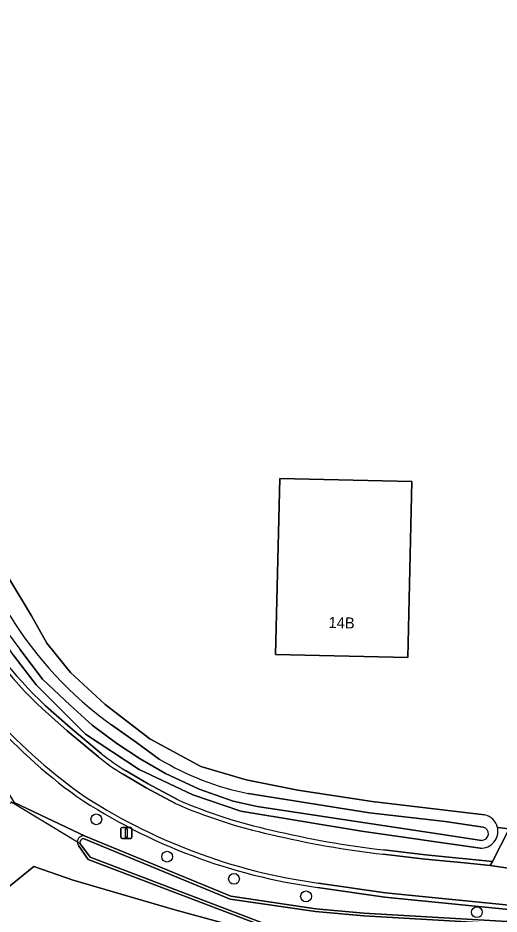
# Model space of a CAD drawing. Extents: x 162510 to 163918, y 388494 to 389774.
# Drawn here: x 162919.9 to 162963.6, y 388968.2 to 389049.6 of the extents above; entities that cross this region are included whole.
import ezdxf

# ---------------------------------------------------------------- set-up
doc = ezdxf.new("R2010")
doc.units = 0
for name, color, linetype in [('IMGEO_Boom', 7, 'Continuous'), ('IMGEO_Duiker', 7, 'Continuous'), ('IMGEO_Erf', 7, 'Continuous'), ('IMGEO_Grasland_agrarisch', 7, 'Continuous'), ('IMGEO_Grasland_overig', 7, 'Continuous'), ('IMGEO_Lichtmast', 7, 'Continuous'), ('IMGEO_Oever', 7, 'Continuous'), ('IMGEO_Pand', 7, 'Continuous'), ('IMGEO_Pand_nummerreeks', 7, 'Continuous'), ('IMGEO_Rijbaan_lokaal_gesloten', 7, 'Continuous'), ('IMGEO_Rijbaan_lokaal_halfverhard', 7, 'Continuous'), ('IMGEO_Rijbaan_lokaal_open', 7, 'Continuous'), ('IMGEO_Waterloop', 7, 'Continuous')]:
    doc.layers.add(name, color=color, linetype=linetype)

msp = doc.modelspace()

# ---------------------------------------------------------------- linework, layer by layer
at = {"layer": 'IMGEO_Boom'}
for centre in [(162927.001, 388976.769), (162933.436, 388973.374), (162939.51, 388971.359), (162946.06, 388969.768), (162961.588, 388968.328)]:
    msp.add_circle(centre, 0.489, dxfattribs=at)
at = {"layer": 'IMGEO_Duiker'}
msp.add_lwpolyline([(162925.55, 388974.52), (162925.278, 388974.684), (162919.381, 388978.255), (162919.231, 388978.346)], dxfattribs=at)
at = {"layer": 'IMGEO_Erf'}
for points in [[(162963.458, 388976.024), (162964.53, 388975.919), (162971.105, 388975.277), (162985.529, 388974.355), (162985.891, 388974.332), (163003.132, 388973.537), (163003.268, 388973.532), (163003.178, 388973.126), (163010.129, 388973.107), (163010.129, 388973.525), (163011.598, 388973.525), (163015.346, 388973.525), (163010.383, 389006.948), (163001.868, 389067.016)], [(162917.331, 389001.487), (162921.109, 388995.245), (162922.506, 388992.781), (162924.641, 388990.111), (162927.804, 388987.195), (162931.869, 388984.074), (162936.51, 388981.566), (162940.613, 388980.351), (162945.319, 388979.431), (162952.054, 388978.404), (162962.289, 388977.181)]]:
    msp.add_lwpolyline(points, dxfattribs=at)
msp.add_lwpolyline([(162955.677, 389007.464), (162955.304, 388991.467), (162943.286, 388991.753), (162943.667, 389007.749)], close=True, dxfattribs=at)
msp.add_arc((162961.959, 388975.679), 1.538, 12.97569, 77.61549, dxfattribs=at)
at = {"layer": 'IMGEO_Grasland_agrarisch'}
msp.add_lwpolyline([(162965.269, 388906.51), (162965.295, 388907.571), (162970.507, 388960.823), (162969.722, 388963.115), (162943.576, 388965.984), (162934.148, 388968.56), (162924.889, 388971.244), (162921.313, 388972.477), (162913.718, 388966.327), (162905.083, 388967.364), (162899.047, 388963.626), (162890.416, 388958.224), (162881.009, 388955.532), (162875.047, 388956.022), (162874.432, 388960.337)], dxfattribs=at)
at = {"layer": 'IMGEO_Grasland_overig'}
for points in [[(162961.88, 388974.143), (162951.099, 388975.683), (162940.134, 388977.514), (162935.781, 388978.992), (162930.904, 388981.309), (162926.018, 388984.505), (162921.542, 388989.001), (162919.446, 388991.713), (162916.571, 388996.046), (162914.292, 388999.844), (162909.816, 389007.729), (162906.182, 389015.741), (162904.051, 389020.029), (162902.408, 389023.626), (162901.284, 389026.429), (162899.191, 389030.377)], [(162890.275, 389028.321), (162906.761, 389000), (162914.021, 388987.018), (162919.521, 388978.287), (162925.982, 388975.254), (162939.232, 388969.776), (162946.964, 388968.638), (162951.321, 388968.254), (162966.391, 388967.363), (162970.783, 388966.255), (162971.31, 388964.515), (162972.188, 388961.62), (162974.481, 388958.888)], [(162922.374, 388987.09), (162924.622, 388985.127), (162927.452, 388982.75)], [(162929.651, 388981.209), (162931.71, 388979.994), (162934.378, 388978.562)], [(162925.982, 388975.254), (162919.521, 388978.287), (162919.381, 388978.255), (162916.496, 388977.585), (162877.491, 388960.617), (162874.432, 388960.337)], [(162953.123, 388973.988), (162956.928, 388973.533), (162962.999, 388972.942), (162964.53, 388975.919), (162963.458, 388976.024)], [(162874.432, 388960.337), (162875.047, 388956.022), (162881.009, 388955.532), (162890.416, 388958.224), (162899.047, 388963.626), (162905.083, 388967.364), (162913.718, 388966.327), (162921.313, 388972.477), (162924.889, 388971.244), (162934.148, 388968.56), (162943.576, 388965.984), (162969.722, 388963.115), (162969.194, 388964.658), (162943.616, 388966.516), (162926.272, 388973.119), (162925.379, 388974.383)], [(162970.158, 388968.16), (162965.692, 388968.446), (162953.235, 388969.706), (162947.107, 388970.584)]]:
    msp.add_lwpolyline(points, dxfattribs=at)
for centre, radius, start, end in [((162953.538, 389019.707), 45.112, 210.91686, 226.30497), ((162955.293, 389020.184), 51.114, 209.11016, 233.98533), ((162938.618, 388996.345), 17.593, 230.60151, 239.35502), ((162954.136, 389022.301), 52.193, 236.37965, 262.25982), ((162952.816, 389020.914), 46.191, 246.47421, 257.64713), ((162962.813, 389058.391), 84.957, 256.46826, 263.45098), ((162961.958, 388975.68), 1.539, 267.0987, 12.91369), ((162925.842, 388974.707), 0.565, 75.64478, 182.34657), ((162925.842, 388974.706), 0.565, 182.22454, 214.87363)]:
    msp.add_arc(centre, radius, start, end, dxfattribs=at)
at = {"layer": 'IMGEO_Lichtmast'}
for p, q in [((162929.236, 388975.135), (162929.236, 388975.935)), ((162929.236, 388975.935), (162929.236, 388975.135)), ((162929.336, 388976.035), (162930.126, 388976.035)), ((162930.126, 388976.035), (162929.336, 388976.035)), ((162930.226, 388975.935), (162930.226, 388975.135)), ((162930.226, 388975.135), (162930.226, 388975.935)), ((162930.126, 388975.035), (162929.336, 388975.035)), ((162929.336, 388975.035), (162930.126, 388975.035))]:
    msp.add_line(p, q, dxfattribs=at)
msp.add_lwpolyline([(162929.656, 388975.91), (162929.806, 388975.91), (162929.806, 388975.16), (162929.656, 388975.16), (162929.656, 388975.91)], dxfattribs=at)
for centre, start, end in [((162929.336, 388975.935), 90, 180), ((162929.336, 388975.935), 90, 180), ((162930.126, 388975.935), 0, 90), ((162930.126, 388975.935), 360, 90), ((162929.336, 388975.135), 180, 270), ((162929.336, 388975.135), 180, 270), ((162930.126, 388975.135), 270, 0), ((162930.126, 388975.135), 270, 0)]:
    msp.add_arc(centre, 0.1, start, end, dxfattribs=at)
at = {"layer": 'IMGEO_Oever'}
for points in [[(162962.289, 388977.181), (162952.054, 388978.404), (162945.319, 388979.431), (162940.613, 388980.351), (162936.51, 388981.566), (162931.869, 388984.074), (162927.804, 388987.195), (162924.641, 388990.111), (162922.506, 388992.781), (162921.109, 388995.245), (162917.331, 389001.487)], [(162962.001, 388974.859), (162959.25, 388975.27), (162941.605, 388977.932), (162939.439, 388978.425), (162936.358, 388979.523), (162933.289, 388980.94), (162930.973, 388982.26), (162928.874, 388983.661), (162926.625, 388985.324), (162924.634, 388987.131), (162922.108, 388989.507), (162920.041, 388992.229)], [(162919.446, 388991.713), (162921.542, 388989.001), (162926.018, 388984.505), (162930.904, 388981.309), (162935.781, 388978.992), (162940.134, 388977.514), (162951.099, 388975.683), (162961.88, 388974.143)], [(162928.367, 388985.352), (162930.666, 388983.75), (162932.72, 388982.251)], [(162940.81, 388979.11), (162951.837, 388977.364)], [(162951.837, 388977.364), (162958.695, 388976.563), (162962.153, 388976.067)], [(162925.911, 388975.006), (162939.163, 388969.527), (162946.934, 388968.383), (162951.302, 388967.998), (162966.352, 388967.108), (162970.579, 388966.042), (162971.064, 388964.44), (162971.927, 388961.595), (162966.53, 388908.206)], [(162966.787, 388908.195), (162972.188, 388961.62), (162971.31, 388964.515), (162970.783, 388966.255), (162966.391, 388967.363), (162951.321, 388968.254), (162946.964, 388968.638), (162939.232, 388969.776), (162925.982, 388975.254)], [(162925.379, 388974.383), (162926.272, 388973.119), (162943.616, 388966.516), (162969.194, 388964.658), (162969.722, 388963.115), (162970.507, 388960.823), (162965.295, 388907.571), (162965.269, 388906.51)], [(162965.551, 388907.555), (162970.768, 388960.853), (162969.965, 388963.198), (162969.382, 388964.902), (162943.672, 388966.769), (162926.437, 388973.331), (162925.55, 388974.52)]]:
    msp.add_lwpolyline(points, dxfattribs=at)
for centre, radius, start, end in [((162985.083, 389040.407), 80.942, 209.85069, 216.52824), ((162948.731, 389013.515), 34.754, 211.65165, 234.13095), ((162945.921, 389004.264), 25.668, 239.04829, 258.5136), ((162961.959, 388975.679), 1.538, 12.97569, 77.61549), ((162961.958, 388975.68), 1.539, 267.0987, 12.91369), ((162962.026, 388975.469), 0.611, 267.61328, 78.0433), ((162925.842, 388974.707), 0.565, 75.64478, 182.34657), ((162925.856, 388974.67), 0.341, 80.66528, 206.12491), ((162925.842, 388974.706), 0.565, 182.22454, 214.87363)]:
    msp.add_arc(centre, radius, start, end, dxfattribs=at)
at = {"layer": 'IMGEO_Pand'}
msp.add_lwpolyline([(162955.304, 388991.467), (162955.677, 389007.464), (162943.667, 389007.749), (162943.286, 388991.753)], close=True, dxfattribs=at)
at = {"layer": 'IMGEO_Rijbaan_lokaal_gesloten'}
for points in [[(162927.195, 388982.444), (162924.365, 388984.821), (162922.098, 388986.801)], [(162934.189, 388978.21), (162931.521, 388979.642), (162929.447, 388980.865)], [(163060.658, 388969.221), (163043.395, 388969.279), (163026.878, 388969.344), (163019.275, 388969.441), (163016.375, 388969.489), (163010.694, 388969.666), (163006.164, 388969.852), (163001.869, 388970.009), (162995.115, 388970.321), (162989.16, 388970.649), (162986.023, 388970.77), (162985.329, 388970.797), (162980.065, 388971.129), (162974.827, 388971.464), (162970.89, 388971.741), (162967.254, 388971.997), (162965.448, 388972.167), (162962.802, 388972.559), (162960.469, 388972.811), (162956.88, 388973.136), (162953.077, 388973.591)], [(162947.161, 388970.98), (162953.292, 388970.102), (162965.732, 388968.844), (162970.174, 388968.559), (162975.389, 388968.225), (162985.053, 388967.564), (162990.798, 388967.159), (162991.481, 388967.111), (163004.846, 388966.436), (163005.318, 388966.412), (163012.759, 388966.272), (163018.447, 388966.138), (163027.251, 388966.034), (163035.819, 388965.997), (163049.064, 388965.828), (163059.249, 388965.846), (163068.574, 388965.898)]]:
    msp.add_lwpolyline(points, dxfattribs=at)
for centre, radius, start, end in [((162953.569, 389019.735), 45.553, 210.93385, 226.30203), ((162955.268, 389020.162), 50.682, 209.10323, 233.99307), ((162938.634, 388996.363), 18.016, 230.58577, 239.34144), ((162954.145, 389022.323), 51.816, 236.40293, 262.25355), ((162952.767, 389020.73), 46.402, 246.39887, 257.65864), ((162962.764, 389058.132), 85.094, 256.46551, 263.46357)]:
    msp.add_arc(centre, radius, start, end, dxfattribs=at)
at = {"layer": 'IMGEO_Rijbaan_lokaal_halfverhard'}
for points in [[(162922.098, 388986.801), (162924.365, 388984.821), (162927.195, 388982.444)], [(162927.452, 388982.75), (162924.622, 388985.127), (162922.374, 388987.09)], [(162929.447, 388980.865), (162931.521, 388979.642), (162934.189, 388978.21)], [(162934.378, 388978.562), (162931.71, 388979.994), (162929.651, 388981.209)], [(162953.077, 388973.591), (162956.88, 388973.136), (162960.469, 388972.811), (162962.802, 388972.559), (162962.999, 388972.942), (162956.928, 388973.533), (162953.123, 388973.988)], [(162947.107, 388970.584), (162953.235, 388969.706), (162965.692, 388968.446), (162970.158, 388968.16), (162970.174, 388968.559), (162965.732, 388968.844), (162953.292, 388970.102), (162947.161, 388970.98)]]:
    msp.add_lwpolyline(points, dxfattribs=at)
for centre, radius, start, end in [((162953.569, 389019.735), 45.553, 210.93385, 226.30203), ((162953.538, 389019.707), 45.112, 210.91686, 226.30497), ((162955.293, 389020.184), 51.114, 209.11016, 233.98533), ((162955.268, 389020.162), 50.682, 209.10323, 233.99307), ((162938.634, 388996.363), 18.016, 230.58577, 239.34144), ((162938.618, 388996.345), 17.593, 230.60151, 239.35502), ((162954.145, 389022.323), 51.816, 236.40293, 262.25355), ((162954.136, 389022.301), 52.193, 236.37965, 262.25982), ((162952.767, 389020.73), 46.402, 246.39887, 257.65864), ((162952.816, 389020.914), 46.191, 246.47421, 257.64713), ((162962.813, 389058.391), 84.957, 256.46826, 263.45098), ((162962.764, 389058.132), 85.094, 256.46551, 263.46357)]:
    msp.add_arc(centre, radius, start, end, dxfattribs=at)
at = {"layer": 'IMGEO_Rijbaan_lokaal_open'}
msp.add_lwpolyline([(162985.529, 388974.355), (162971.105, 388975.277), (162964.53, 388975.919), (162962.999, 388972.942), (162962.802, 388972.559), (162965.448, 388972.167), (162967.254, 388971.997), (162970.89, 388971.741), (162974.827, 388971.464), (162980.065, 388971.129), (162985.329, 388970.797)], close=True, dxfattribs=at)
at = {"layer": 'IMGEO_Waterloop'}
for points in [[(162920.041, 388992.229), (162922.108, 388989.507), (162924.634, 388987.131), (162926.625, 388985.324), (162928.874, 388983.661), (162930.973, 388982.26), (162933.289, 388980.94), (162936.358, 388979.523), (162939.439, 388978.425), (162941.605, 388977.932), (162959.25, 388975.27), (162962.001, 388974.859)], [(162932.72, 388982.251), (162930.666, 388983.75), (162928.367, 388985.352)], [(162962.153, 388976.067), (162958.695, 388976.563), (162951.837, 388977.364), (162940.81, 388979.11)], [(162966.53, 388908.206), (162971.927, 388961.595), (162971.064, 388964.44), (162970.579, 388966.042), (162966.352, 388967.108), (162951.302, 388967.998), (162946.934, 388968.383), (162939.163, 388969.527), (162925.911, 388975.006)], [(162925.55, 388974.52), (162926.437, 388973.331), (162943.672, 388966.769), (162969.382, 388964.902), (162969.965, 388963.198), (162970.768, 388960.853), (162965.551, 388907.555)]]:
    msp.add_lwpolyline(points, dxfattribs=at)
for centre, radius, start, end in [((162985.083, 389040.407), 80.942, 209.85069, 216.52824), ((162948.731, 389013.515), 34.754, 211.65165, 234.13095), ((162945.921, 389004.264), 25.668, 239.04829, 258.5136), ((162962.026, 388975.469), 0.611, 267.61328, 78.0433), ((162925.856, 388974.67), 0.341, 80.66528, 206.12491)]:
    msp.add_arc(centre, radius, start, end, dxfattribs=at)

# ---------------------------------------------------------------- texts
at = {"layer": 'IMGEO_Pand_nummerreeks'}
msp.add_text('14B', height=1, rotation=358.63675, dxfattribs=at).set_placement((162948.09, 388994.159))

doc.saveas('drawing.dxf')
